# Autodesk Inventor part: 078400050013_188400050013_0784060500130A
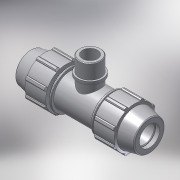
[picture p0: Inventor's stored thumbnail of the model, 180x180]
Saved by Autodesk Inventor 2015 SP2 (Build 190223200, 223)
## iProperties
Created: 2017-02
Part Number: 078400050013_188400050013_0784060500130A
Material: PVC-Piping
Description: PLASSON TEE WITH THREADED MALE OFFTAKE 50-1.1/4"-50
Document SubType Name: Modeling
Designer: KIM
Mass: 92.6774 g
Surface Area: 199.44 cm^2
Volume: 66.1981 cm^3
Density: 1.4 g/cm^3
Appearance: Smooth - White
Author: Кирилл
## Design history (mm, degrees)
derived "07840.ipt"
feature "Solid1::07840.ipt"
feature "Solid2::07840.ipt"
tag "TaggingFeature1"
body "Solid1"
body "Solid2"
other parameters: "d4" = 9.58333, "d5" = 27.6, "d7" = 96, "d11" = 3.83333, "d13" = 120 deg, "d14" = 75, "d15" = 12 deg, "d16" = 83.52, "d18" = 2.5, "d19" = 35 deg, "d20" = 17.5 deg, "d21" = 89.28, "d23" = 0, "d25" = 360 deg, "d27" = 1.92, "d33" = 1, "d42" = 41.4, "d43" = 2.88, "d46" = 1.5, "d68" = 3.83333, "d72" = 77, "d73" = 41.91, "d74" = 22, "d75" = 48.1965, "d76" = 29.337, "d77" = 26.4, "d80" = 1.2573, "d91" = 72, "d93" = 93, "d95" = 45, "d101" = 0, "d103" = 0, "d105" = 0, "E_" = 96, "A_" = 77, "l_" = 93, "l_2" = 22, "R_" = 41.91
